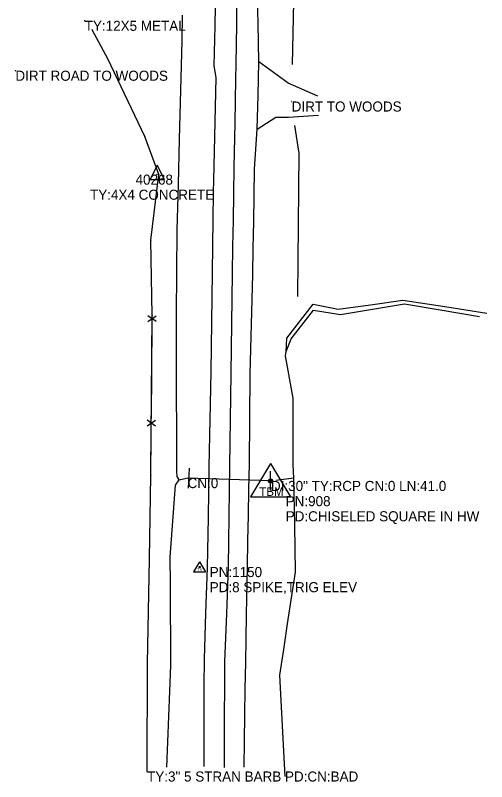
# Model space of a CAD drawing. Extents: x 1445297 to 1476720, y 2042269 to 2057889.
# Drawn here: x 1476114.3 to 1476348.5, y 2054357.8 to 2054738.4 of the extents above; entities that cross this region are included whole.
import ezdxf

# ---------------------------------------------------------------- set-up
doc = ezdxf.new("R2010")
doc.units = 0
for name, color, linetype in [('S_CROSS_DRAIN', 7, 'Continuous'), ('S_CROSS_DRAIN_ANNOT', 7, 'Continuous'), ('S_DITCHLINE', 7, 'Continuous'), ('S_DRG_PT_SYM', 7, 'Continuous'), ('S_EDGE_PAVEMENT', 7, 'Continuous'), ('S_EXIST_ROW', 7, 'Continuous'), ('S_EXIST_ROW_ANNOT', 7, 'Continuous'), ('S_FENCE', 7, 'Continuous'), ('S_FENCE_ANNOT', 7, 'Continuous'), ('S_GATE_ANNOT', 7, 'Continuous'), ('S_HEADWALL', 7, 'Continuous'), ('S_MSC_PT_SYM', 7, 'Continuous'), ('S_PAVEMENT_CROWN', 7, 'Continuous'), ('S_PRIMARY_CTL', 7, 'Continuous'), ('S_PRIMARY_CTL_ANNOT', 7, 'Continuous'), ('S_SECONDARY_CTL', 7, 'Continuous'), ('S_SECONDARY_CTL_ANNOT', 7, 'Continuous'), ('S_SURVEY_TEXT_ANNOT', 7, 'Continuous'), ('S_TRAILS', 7, 'Continuous')]:
    doc.layers.add(name, color=color, linetype=linetype)

msp = doc.modelspace()

# ---------------------------------------------------------------- linework, layer by layer
at = {"layer": 'S_CROSS_DRAIN'}
msp.add_line((1476241.33, 2054507.13), (1476199.93, 2054508.56), dxfattribs=at)
at = {"layer": 'S_DITCHLINE'}
for points in [[(1476251.96, 2054713.86), (1476252.3, 2054729.43), (1476252.65, 2054745)], [(1476189.54, 2054364.95), (1476190.07, 2054377.57), (1476190.59, 2054390.19), (1476191.12, 2054402.8), (1476191.65, 2054415.42), (1476191.56, 2054428.88), (1476191.48, 2054442.34), (1476191.39, 2054455.8), (1476191.31, 2054469.26), (1476192.58, 2054487.18), (1476193.85, 2054505.1), (1476195.67, 2054507.6), (1476194.69, 2054509.31), (1476194.58, 2054511.99), (1476194.52, 2054531.48), (1476194.47, 2054550.98), (1476194.41, 2054570.48), (1476194.36, 2054589.98), (1476194.58, 2054610.86), (1476194.79, 2054631.74), (1476195.34, 2054654.27), (1476195.9, 2054676.81), (1476196.58, 2054701.26), (1476197.26, 2054725.7), (1476197.33, 2054738.49)], [(1476254.64, 2054598.73), (1476254.82, 2054616.52), (1476255.01, 2054634.32), (1476255.19, 2054652.12), (1476255.37, 2054669.91), (1476253.14, 2054683.65)], [(1476248.33, 2054360.26), (1476247.67, 2054372.87), (1476247.01, 2054385.48), (1476246.35, 2054398.09), (1476245.69, 2054410.7), (1476247.66, 2054423.47), (1476249.62, 2054436.24), (1476251.58, 2054449.02), (1476253.54, 2054461.79), (1476253.14, 2054485.17), (1476252.73, 2054508.55), (1476252.3, 2054515.25), (1476252.33, 2054531.75), (1476252.35, 2054548.25), (1476248.49, 2054569.28), (1476248.85, 2054571.34), (1476251.4, 2054577.68), (1476262.53, 2054591.87), (1476275.8, 2054589.83), (1476291.76, 2054592.48), (1476307.72, 2054595.14), (1476326.34, 2054591.95), (1476344.95, 2054588.76)], [(1476248.85, 2054571.34), (1476249.25, 2054577.95), (1476262.32, 2054594.96), (1476274.76, 2054592.37), (1476290.83, 2054594.62), (1476306.9, 2054596.87), (1476327.7, 2054593.69), (1476348.5, 2054590.52)], [(1476195.67, 2054507.6), (1476199.35, 2054508.47)], [(1476252.73, 2054508.55), (1476243.73, 2054507.37)]]:
    msp.add_lwpolyline(points, dxfattribs=at)
at = {"layer": 'S_DRG_PT_SYM'}
for points in [[(1476199.93, 2054508.56), (1476199.93, 2054508.61), (1476199.93, 2054508.56), (1476199.88, 2054508.56), (1476199.93, 2054508.56), (1476199.93, 2054508.51), (1476199.93, 2054508.56), (1476199.98, 2054508.56)], [(1476241.33, 2054507.13), (1476241.33, 2054507.18), (1476241.33, 2054507.13), (1476241.28, 2054507.13), (1476241.33, 2054507.13), (1476241.33, 2054507.08), (1476241.33, 2054507.13), (1476241.38, 2054507.13)]]:
    msp.add_lwpolyline(points, dxfattribs=at)
at = {"layer": 'S_EDGE_PAVEMENT'}
for points in [[(1476208.07, 2054365.33), (1476208.12, 2054378.65), (1476208.16, 2054391.98), (1476208.21, 2054405.31), (1476208.26, 2054418.63), (1476209.04, 2054441.42), (1476209.81, 2054464.2), (1476210.26, 2054489.12), (1476210.71, 2054514.05), (1476211.19, 2054537.68), (1476211.68, 2054561.31), (1476211.94, 2054585.97), (1476212.21, 2054610.63), (1476212.43, 2054623.83), (1476212.64, 2054637.03), (1476212.86, 2054650.23), (1476213.07, 2054663.43), (1476213.61, 2054685.42), (1476214.16, 2054707.4), (1476213.17, 2054713.29), (1476213.56, 2054733.17), (1476213.95, 2054753.04)], [(1476227.98, 2054364.96), (1476228.19, 2054377.95), (1476228.39, 2054390.95), (1476228.6, 2054403.94), (1476228.8, 2054416.93), (1476229.24, 2054440.78), (1476229.68, 2054464.64), (1476229.92, 2054477.39), (1476230.16, 2054490.13), (1476230.4, 2054502.88), (1476230.64, 2054515.63), (1476230.82, 2054538), (1476231, 2054560.37), (1476231.69, 2054584.96), (1476232.37, 2054609.56), (1476232.57, 2054622.65), (1476232.77, 2054635.75), (1476232.97, 2054648.85), (1476233.17, 2054661.95), (1476234.52, 2054681.87), (1476234.9, 2054698.55), (1476235.27, 2054715.23), (1476234.92, 2054734.25), (1476234.56, 2054753.27)]]:
    msp.add_lwpolyline(points, dxfattribs=at)
at = {"layer": 'S_EXIST_ROW'}
for p, q in [((1476184.77, 2054663.98), (1476181.25, 2054656.89)), ((1476184.77, 2054663.98), (1476188.26, 2054656.89)), ((1476184.76, 2054659.26), (1476184.76, 2054659.26)), ((1476181.25, 2054656.89), (1476188.26, 2054656.89))]:
    msp.add_line(p, q, dxfattribs=at)
for radius in [0.12, 0.06]:
    msp.add_circle((1476184.76, 2054659.26), radius, dxfattribs=at)
at = {"layer": 'S_FENCE'}
for p, q in [((1476160.23, 2054716.74), (1476152.44, 2054731.13)), ((1476178.72, 2054678.13), (1476160.23, 2054716.74)), ((1476185.59, 2054659.24), (1476178.72, 2054678.13)), ((1476181.59, 2054626.61), (1476185.59, 2054659.24)), ((1476182.28, 2054589.4), (1476181.59, 2054626.61)), ((1476180.21, 2054586.29), (1476184.33, 2054589.13)), ((1476184.3, 2054586.27), (1476180.23, 2054589.16)), ((1476181.71, 2054509.89), (1476182.28, 2054589.4)), ((1476179.84, 2054534.41), (1476183.96, 2054537.25)), ((1476183.94, 2054534.38), (1476179.86, 2054537.28)), ((1476180.98, 2054468.43), (1476181.71, 2054509.89)), ((1476179.99, 2054416.49), (1476180.98, 2054468.43)), ((1476179.79, 2054362.84), (1476179.99, 2054416.49))]:
    msp.add_line(p, q, dxfattribs=at)
for points in [[(1476160.23, 2054716.74), (1476152.44, 2054731.13)], [(1476178.72, 2054678.13), (1476160.23, 2054716.74)], [(1476185.59, 2054659.24), (1476178.72, 2054678.13)], [(1476181.59, 2054626.61), (1476185.59, 2054659.24)], [(1476182.28, 2054589.4), (1476181.59, 2054626.61)], [(1476181.92, 2054538.19), (1476182.25, 2054585.36)], [(1476181.71, 2054509.89), (1476181.88, 2054533.47)], [(1476180.98, 2054468.43), (1476181.71, 2054509.89)], [(1476179.99, 2054416.49), (1476180.98, 2054468.43)], [(1476179.79, 2054362.84), (1476179.99, 2054416.49)]]:
    msp.add_lwpolyline(points, dxfattribs=at)
at = {"layer": 'S_HEADWALL'}
for points in [[(1476200.62, 2054513.4), (1476200.21, 2054503.59)], [(1476240.93, 2054512.03), (1476240.86, 2054502.31)]]:
    msp.add_lwpolyline(points, dxfattribs=at)
at = {"layer": 'S_MSC_PT_SYM'}
for points in [[(1476148.81, 2054735.65), (1476148.81, 2054735.7), (1476148.81, 2054735.65), (1476148.76, 2054735.65), (1476148.81, 2054735.65), (1476148.81, 2054735.6), (1476148.81, 2054735.65), (1476148.86, 2054735.65)], [(1476152.44, 2054731.13), (1476152.44, 2054731.18), (1476152.44, 2054731.13), (1476152.39, 2054731.13), (1476152.44, 2054731.13), (1476152.44, 2054731.08), (1476152.44, 2054731.13), (1476152.49, 2054731.13)], [(1476160.23, 2054716.74), (1476160.23, 2054716.79), (1476160.23, 2054716.74), (1476160.18, 2054716.74), (1476160.23, 2054716.74), (1476160.23, 2054716.69), (1476160.23, 2054716.74), (1476160.28, 2054716.74)], [(1476114.38, 2054710.85), (1476114.38, 2054710.9), (1476114.38, 2054710.85), (1476114.33, 2054710.85), (1476114.38, 2054710.85), (1476114.38, 2054710.8), (1476114.38, 2054710.85), (1476114.43, 2054710.85)], [(1476251.64, 2054695.56), (1476251.64, 2054695.61), (1476251.64, 2054695.56), (1476251.59, 2054695.56), (1476251.64, 2054695.56), (1476251.64, 2054695.51), (1476251.64, 2054695.56), (1476251.69, 2054695.56)], [(1476178.72, 2054678.13), (1476178.72, 2054678.18), (1476178.72, 2054678.13), (1476178.67, 2054678.13), (1476178.72, 2054678.13), (1476178.72, 2054678.08), (1476178.72, 2054678.13), (1476178.77, 2054678.13)], [(1476185.59, 2054659.24), (1476185.59, 2054659.29), (1476185.59, 2054659.24), (1476185.54, 2054659.24), (1476185.59, 2054659.24), (1476185.59, 2054659.19), (1476185.59, 2054659.24), (1476185.64, 2054659.24)], [(1476181.59, 2054626.61), (1476181.59, 2054626.66), (1476181.59, 2054626.61), (1476181.54, 2054626.61), (1476181.59, 2054626.61), (1476181.59, 2054626.56), (1476181.59, 2054626.61), (1476181.64, 2054626.61)], [(1476182.28, 2054589.4), (1476182.28, 2054589.45), (1476182.28, 2054589.4), (1476182.23, 2054589.4), (1476182.28, 2054589.4), (1476182.28, 2054589.35), (1476182.28, 2054589.4), (1476182.33, 2054589.4)], [(1476181.71, 2054509.89), (1476181.71, 2054509.94), (1476181.71, 2054509.89), (1476181.66, 2054509.89), (1476181.71, 2054509.89), (1476181.71, 2054509.84), (1476181.71, 2054509.89), (1476181.76, 2054509.89)], [(1476180.98, 2054468.43), (1476180.98, 2054468.48), (1476180.98, 2054468.43), (1476180.93, 2054468.43), (1476180.98, 2054468.43), (1476180.98, 2054468.38), (1476180.98, 2054468.43), (1476181.03, 2054468.43)], [(1476179.99, 2054416.49), (1476179.99, 2054416.54), (1476179.99, 2054416.49), (1476179.94, 2054416.49), (1476179.99, 2054416.49), (1476179.99, 2054416.44), (1476179.99, 2054416.49), (1476180.04, 2054416.49)], [(1476179.79, 2054362.84), (1476179.79, 2054362.89), (1476179.79, 2054362.84), (1476179.74, 2054362.84), (1476179.79, 2054362.84), (1476179.79, 2054362.79), (1476179.79, 2054362.84), (1476179.84, 2054362.84)]]:
    msp.add_lwpolyline(points, dxfattribs=at)
at = {"layer": 'S_PAVEMENT_CROWN'}
msp.add_lwpolyline([(1476218.26, 2054364.84), (1476218.3, 2054378.01), (1476218.33, 2054391.19), (1476218.37, 2054404.36), (1476218.4, 2054417.53), (1476219.36, 2054441.06), (1476220.31, 2054464.6), (1476220.47, 2054477.11), (1476220.63, 2054489.62), (1476220.79, 2054502.13), (1476220.95, 2054514.65), (1476221.22, 2054537.59), (1476221.49, 2054560.53), (1476221.85, 2054585.34), (1476222.21, 2054610.15), (1476222.44, 2054623.36), (1476222.67, 2054636.57), (1476222.89, 2054649.78), (1476223.12, 2054662.99), (1476223.52, 2054684.94), (1476223.91, 2054706.89), (1476224.07, 2054714.04), (1476224.32, 2054733.72), (1476224.58, 2054753.41)], dxfattribs=at)
at = {"layer": 'S_PRIMARY_CTL'}
for p, q in [((1476241.14, 2054515.78), (1476231.1, 2054499.27)), ((1476241.14, 2054515.78), (1476250.96, 2054499.27)), ((1476231.1, 2054499.27), (1476250.96, 2054499.27))]:
    msp.add_line(p, q, dxfattribs=at)
for radius in [1.04, 0.609, 0.344]:
    msp.add_circle((1476241.14, 2054507.08), radius, dxfattribs=at)
at = {"layer": 'S_SECONDARY_CTL'}
for p, q in [((1476205.9, 2054466.98), (1476202.89, 2054462.02)), ((1476205.9, 2054466.98), (1476208.84, 2054462.02)), ((1476202.89, 2054462.02), (1476208.84, 2054462.02))]:
    msp.add_line(p, q, dxfattribs=at)
for radius in [0.311, 0.183, 0.103]:
    msp.add_circle((1476205.9, 2054464.37), radius, dxfattribs=at)
at = {"layer": 'S_TRAILS'}
for points in [[(1476264.7, 2054698.14), (1476249.9, 2054704.64), (1476235.27, 2054715.23)], [(1476234.52, 2054681.87), (1476243.79, 2054687.78), (1476250.01, 2054687.71), (1476264.89, 2054688.73)]]:
    msp.add_lwpolyline(points, dxfattribs=at)

# ---------------------------------------------------------------- texts
at = {"layer": 'S_CROSS_DRAIN_ANNOT'}
for s, p in [('CN:0', (1476199.93, 2054503.56)), ('DI:30" TY:RCP CN:0 LN:41.0', (1476241.33, 2054502.13))]:
    msp.add_text(s, height=5, dxfattribs=at).set_placement(p)
at = {"layer": 'S_EXIST_ROW_ANNOT'}
for s, p in [('40268', (1476174.05, 2054654.26)), ('TY:4X4 CONCRETE', (1476151.45, 2054646.76))]:
    msp.add_text(s, height=5, dxfattribs=at).set_placement(p)
at = {"layer": 'S_FENCE_ANNOT'}
msp.add_text('TY:3" 5 STRAN BARB PD:CN:BAD', height=5, dxfattribs=at).set_placement((1476179.79, 2054357.84))
at = {"layer": 'S_GATE_ANNOT'}
msp.add_text('TY:12X5 METAL', height=5, dxfattribs=at).set_placement((1476148.81, 2054730.65))
at = {"layer": 'S_PRIMARY_CTL'}
msp.add_text('TBM', height=4.287, dxfattribs=at).set_placement((1476235.49, 2054499.69))
at = {"layer": 'S_PRIMARY_CTL_ANNOT'}
for s, p in [('PN:908', (1476248.64, 2054494.58)), ('PD:CHISELED SQUARE IN HW', (1476248.64, 2054487.08))]:
    msp.add_text(s, height=5, dxfattribs=at).set_placement(p)
at = {"layer": 'S_SECONDARY_CTL'}
msp.add_text('TV', height=1.5, dxfattribs=at).set_placement((1476204.69, 2054462.36))
at = {"layer": 'S_SECONDARY_CTL_ANNOT'}
for s, p in [('PN:1150', (1476210.9, 2054459.37)), ('PD:8 SPIKE,TRIG ELEV', (1476210.9, 2054451.87))]:
    msp.add_text(s, height=5, dxfattribs=at).set_placement(p)
at = {"layer": 'S_SURVEY_TEXT_ANNOT'}
for s, p in [('DIRT ROAD TO WOODS', (1476114.38, 2054705.85)), ('DIRT TO WOODS', (1476251.64, 2054690.56))]:
    msp.add_text(s, height=5, dxfattribs=at).set_placement(p)

doc.saveas('drawing.dxf')
